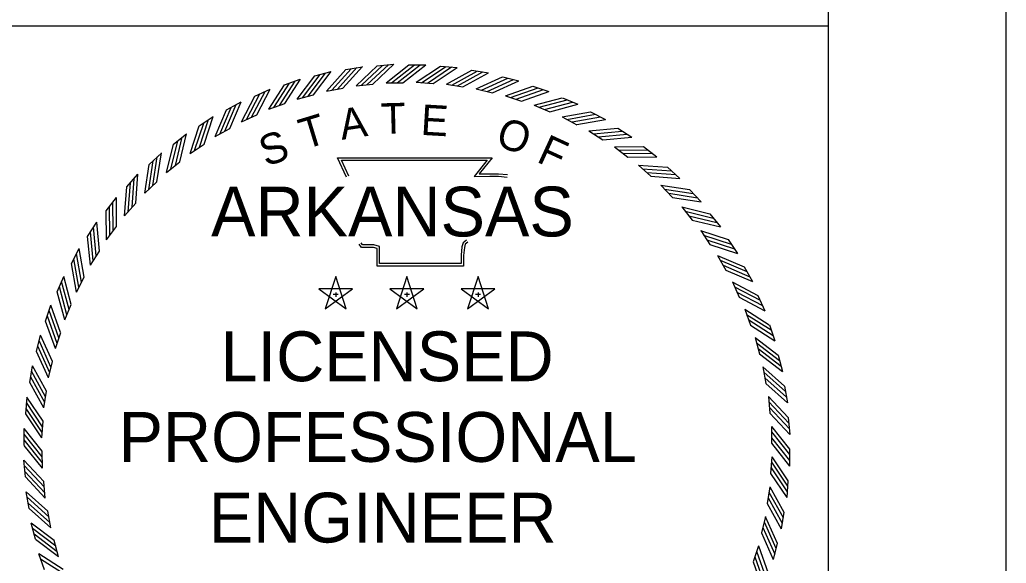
# Model space of a CAD drawing. Extents: x 0 to 1228740, y 0 to 152440.
# Drawn here: x 30.801 to 34, y 18.4 to 20.162 of the extents above; entities that cross this region are included whole.
import ezdxf

# ---------------------------------------------------------------- set-up
doc = ezdxf.new("R2010")
doc.units = 0
doc.layers.add('R_Border', color=7, linetype='Continuous')
doc.layers.add('STAMP', color=7, linetype='Continuous')

msp = doc.modelspace()

# ---------------------------------------------------------------- linework, layer by layer
at = {"layer": 'R_Border'}
for p, q in [((33.4231, 0.5768), (33.4231, 21.4232)), ((29.1131, 20.1432), (33.4231, 20.1432))]:
    msp.add_line(p, q, dxfattribs=at)
msp.add_lwpolyline([(33.9999, 22), (0, 22), (0, 0), (33.9999, 0)], close=True, dxfattribs=at)
at = {"layer": 'STAMP'}
for p, q in [((31.758, 19.9803), (31.8106, 19.9941)), ((31.8584, 20.0008), (31.912, 20.0102)), ((31.9602, 20.013), (32.0144, 20.018)), ((32.0632, 20.016), (32.1176, 20.016)), ((32.1651, 20.0119), (32.2193, 20.0079)), ((32.2668, 19.9987), (32.3205, 19.9903)), ((31.6595, 19.9515), (31.7108, 19.9697)), ((32.367, 19.9772), (32.4199, 19.9643)), ((31.5638, 19.9147), (31.6134, 19.937)), ((31.7954, 19.9309), (31.8491, 19.9404)), ((31.8916, 19.9485), (31.9459, 19.9535)), ((31.989, 19.9581), (32.0435, 19.9581)), ((32.0868, 19.9596), (32.1412, 19.9556)), ((32.1845, 19.9531), (32.2383, 19.9446)), ((32.2812, 19.9385), (32.3342, 19.9256)), ((32.4651, 19.9474), (32.5167, 19.9302)), ((31.7009, 19.9054), (31.7536, 19.9193)), ((32.3764, 19.9159), (32.4281, 19.8987)), ((32.5605, 19.9097), (32.6105, 19.8883)), ((31.4715, 19.8702), (31.5191, 19.8965)), ((31.6089, 19.8722), (31.6603, 19.8904)), ((32.4695, 19.8856), (32.5196, 19.8642)), ((31.3831, 19.8181), (31.4284, 19.8483)), ((31.5199, 19.8315), (31.5696, 19.8539)), ((32.5597, 19.8477), (32.6078, 19.8222)), ((32.6523, 19.8642), (32.7004, 19.8387)), ((31.4346, 19.7836), (31.4823, 19.81)), ((32.6464, 19.8025), (32.6923, 19.7731)), ((32.7402, 19.8112), (32.786, 19.7819)), ((31.2994, 19.759), (31.342, 19.7928)), ((31.3535, 19.7288), (31.3988, 19.7591)), ((32.7292, 19.7503), (32.7725, 19.7172)), ((32.8233, 19.7512), (32.8665, 19.7182)), ((31.2208, 19.6931), (31.2605, 19.7303)), ((31.2772, 19.6675), (31.3199, 19.7014)), ((32.8073, 19.6914), (32.8478, 19.6548)), ((32.9012, 19.6846), (32.9415, 19.6481)), ((31.148, 19.621), (31.1844, 19.6614)), ((31.2063, 19.6001), (31.246, 19.6374)), ((32.8803, 19.6262), (32.9176, 19.5865)), ((32.9733, 19.6117), (33.0105, 19.572)), ((31.0813, 19.5431), (31.1143, 19.5863)), ((31.1411, 19.5271), (31.1777, 19.5676)), ((32.9477, 19.5553), (32.9816, 19.5126)), ((33.0392, 19.5331), (33.073, 19.4905)), ((31.0213, 19.46), (31.0506, 19.5058)), ((31.0822, 19.449), (31.1153, 19.4923)), ((33.009, 19.479), (33.0392, 19.4337)), ((30.9684, 19.3721), (30.9938, 19.4202)), ((33.0983, 19.4494), (33.1285, 19.4041)), ((31.03, 19.3662), (31.0594, 19.4121)), ((33.0638, 19.3979), (33.0902, 19.3502)), ((33.1504, 19.361), (33.1767, 19.3134)), ((30.9228, 19.2803), (30.9442, 19.3303)), ((30.9848, 19.2795), (31.0103, 19.3277)), ((31.8255, 19.3297), (31.7915, 19.2253)), ((31.8594, 19.2254), (31.8256, 19.3298)), ((32.0562, 19.3297), (32.0222, 19.2253)), ((32.0901, 19.2254), (32.0563, 19.3298)), ((32.287, 19.3297), (32.2529, 19.2253)), ((32.3209, 19.2254), (32.287, 19.3298)), ((31.8804, 19.2899), (31.7706, 19.29)), ((31.7707, 19.2899), (31.8594, 19.2252)), ((31.7916, 19.2254), (31.8805, 19.2898)), ((32.1111, 19.2899), (32.0013, 19.29)), ((32.0014, 19.2899), (32.0902, 19.2252)), ((32.0223, 19.2254), (32.1112, 19.2898)), ((32.3418, 19.2899), (32.232, 19.29)), ((32.2321, 19.2899), (32.3209, 19.2252)), ((32.2531, 19.2254), (32.342, 19.2898)), ((33.1117, 19.3126), (33.1341, 19.2629)), ((31.8177, 19.2723), (31.834, 19.2723)), ((31.8256, 19.2782), (31.8256, 19.2644)), ((32.0484, 19.2723), (32.0647, 19.2723)), ((32.0563, 19.2782), (32.0563, 19.2644)), ((32.2791, 19.2723), (32.2955, 19.2723)), ((32.2871, 19.2782), (32.2871, 19.2644)), ((33.1949, 19.2687), (33.2172, 19.2191)), ((30.8851, 19.1849), (30.9023, 19.2365)), ((30.9469, 19.1893), (30.9683, 19.2394)), ((33.1524, 19.2236), (33.1706, 19.1722)), ((33.2317, 19.173), (33.2498, 19.1217)), ((30.8553, 19.0868), (30.8682, 19.1397)), ((30.9166, 19.0962), (30.9338, 19.148)), ((33.1856, 19.1316), (33.1995, 19.0789)), ((33.2605, 19.0745), (33.2743, 19.0219)), ((30.8338, 18.9866), (30.8422, 19.0403)), ((30.894, 19.001), (30.9069, 19.054)), ((33.2111, 19.0371), (33.2206, 18.9835)), ((33.281, 18.9741), (33.2904, 18.9205)), ((30.8206, 18.8849), (30.8246, 18.9391)), ((30.8794, 18.9043), (30.8879, 18.9581)), ((33.2287, 18.9409), (33.2337, 18.8866)), ((30.8729, 18.8066), (30.8769, 18.861)), ((33.2383, 18.8435), (33.2388, 18.789)), ((33.2932, 18.8723), (33.2982, 18.8181)), ((30.8158, 18.7825), (30.8153, 18.8369)), ((30.8744, 18.7088), (30.8739, 18.7633)), ((33.2398, 18.7457), (33.2358, 18.6913)), ((33.2969, 18.7698), (33.2974, 18.7154)), ((30.8195, 18.68), (30.8145, 18.7342)), ((30.884, 18.6114), (30.879, 18.6657)), ((33.2921, 18.6674), (33.2881, 18.6132)), ((30.8317, 18.5782), (30.8223, 18.6318)), ((33.2333, 18.648), (33.2248, 18.5942)), ((30.9016, 18.5152), (30.8921, 18.5689)), ((33.2789, 18.5657), (33.2705, 18.512)), ((30.8522, 18.4778), (30.8384, 18.5304)), ((33.2187, 18.5513), (33.2058, 18.4983)), ((30.9271, 18.4207), (30.9132, 18.4734)), ((33.2574, 18.4655), (33.2445, 18.4126)), ((30.881, 18.3793), (30.8628, 18.4306)), ((33.1961, 18.4561), (33.1789, 18.4044))]:
    msp.add_line(p, q, dxfattribs=at)
for points in [[(31.7535, 19.9193), (31.8106, 19.9942)], [(31.7953, 19.9309), (31.8583, 20.0007)], [(31.8126, 19.9337), (31.8756, 20.0036)], [(31.8311, 19.9374), (31.8941, 20.0073)], [(31.849, 19.9404), (31.912, 20.0103)], [(31.8916, 19.9485), (31.9601, 20.0129)], [(31.909, 19.9499), (31.9776, 20.0144)], [(31.9278, 19.9521), (31.9964, 20.0165)], [(31.9458, 19.9536), (32.0144, 20.018)], [(31.9889, 19.9581), (32.0631, 20.0159)], [(32.0064, 19.9579), (32.0806, 20.0158)], [(32.0253, 19.9583), (32.0995, 20.0162)], [(32.0434, 19.9582), (32.1177, 20.016)], [(32.0868, 19.9596), (32.165, 20.0119)], [(32.1042, 19.9582), (32.1825, 20.0104)], [(32.1231, 19.9572), (32.2013, 20.0095)], [(32.1411, 19.9557), (32.2194, 20.008)], [(32.1844, 19.953), (32.2667, 19.9987)], [(32.2016, 19.9502), (32.284, 19.9958)], [(32.2204, 19.9476), (32.3027, 19.9933)], [(31.643, 19.8845), (31.6937, 19.9638)], [(31.6602, 19.8904), (31.7109, 19.9697)], [(31.7008, 19.9054), (31.7579, 19.9802)], [(31.7178, 19.9096), (31.7749, 19.9845)], [(31.736, 19.9149), (31.793, 19.9897)], [(32.2383, 19.9447), (32.3206, 19.9903)], [(32.2811, 19.9385), (32.3669, 19.9771)], [(32.2981, 19.9342), (32.3839, 19.9728)], [(32.3166, 19.9301), (32.4024, 19.9688)], [(32.3341, 19.9256), (32.4199, 19.9643)], [(31.5529, 19.8466), (31.5969, 19.9298)], [(31.5695, 19.8539), (31.6135, 19.9371)], [(31.6088, 19.8721), (31.6595, 19.9514)], [(31.6254, 19.8778), (31.676, 19.9571)], [(32.3763, 19.9159), (32.465, 19.9474)], [(32.3929, 19.9102), (32.4816, 19.9417)], [(32.411, 19.9047), (32.4997, 19.9361)], [(32.4281, 19.8988), (32.5168, 19.9302)], [(31.5198, 19.8314), (31.5638, 19.9147)], [(31.5359, 19.8385), (31.5798, 19.9217)], [(32.4694, 19.8856), (32.5604, 19.9096)], [(32.4854, 19.8786), (32.5764, 19.9026)], [(31.4345, 19.7835), (31.4714, 19.8701)], [(31.4499, 19.7919), (31.4868, 19.8784)], [(31.4662, 19.8014), (31.5032, 19.8879)], [(31.4822, 19.81), (31.5191, 19.8966)], [(32.5029, 19.8715), (32.5939, 19.8956)], [(32.5195, 19.8642), (32.6105, 19.8883)], [(31.3836, 19.7491), (31.4133, 19.8385)], [(31.3988, 19.759), (31.4284, 19.8484)], [(32.5596, 19.8477), (32.6522, 19.8641)], [(32.575, 19.8394), (32.6676, 19.8558)], [(32.5919, 19.8309), (32.6845, 19.8473)], [(32.6078, 19.8223), (32.7005, 19.8387)], [(31.3535, 19.7287), (31.3831, 19.8181)], [(31.3681, 19.7383), (31.3978, 19.8276)], [(32.6463, 19.8025), (32.7401, 19.8112)], [(32.661, 19.7929), (32.7547, 19.8016)], [(31.291, 19.6782), (31.3132, 19.7697)], [(31.3056, 19.6903), (31.3277, 19.7817)], [(31.3199, 19.7014), (31.342, 19.7929)], [(32.6771, 19.7831), (32.7709, 19.7918)], [(32.6923, 19.7732), (32.786, 19.7819)], [(31.2772, 19.6674), (31.2994, 19.7589)], [(32.7291, 19.7503), (32.8232, 19.7512)], [(32.7429, 19.7395), (32.837, 19.7405)], [(31.2326, 19.6251), (31.2472, 19.7181)], [(31.246, 19.6374), (31.2605, 19.7304)], [(31.8606, 19.652), (31.8316, 19.7147), (32.3332, 19.715), (32.2913, 19.6624), (32.3254, 19.6628), (32.3539, 19.6632), (32.3823, 19.6601)], [(31.8678, 19.6553), (31.844, 19.7068), (32.3167, 19.7071), (32.2747, 19.6542), (32.3255, 19.6549), (32.3535, 19.6552), (32.3814, 19.6522)], [(32.7582, 19.7284), (32.8523, 19.7293)], [(32.7725, 19.7172), (32.8666, 19.7182)], [(31.2063, 19.6001), (31.2208, 19.693)], [(31.2191, 19.6119), (31.2337, 19.7049)], [(32.8072, 19.6914), (32.9011, 19.6846)], [(32.8201, 19.6795), (32.914, 19.6727)], [(31.1653, 19.5542), (31.1722, 19.6481)], [(31.1776, 19.5675), (31.1844, 19.6614)], [(32.8344, 19.6672), (32.9283, 19.6604)], [(32.8477, 19.6549), (32.9416, 19.6481)], [(31.1411, 19.527), (31.1479, 19.6209)], [(31.153, 19.5399), (31.1598, 19.6338)], [(32.8802, 19.6262), (32.9732, 19.6117)], [(32.8921, 19.6134), (32.9851, 19.5988)], [(31.1153, 19.4923), (31.1143, 19.5864)], [(32.9053, 19.5999), (32.9983, 19.5853)], [(32.9176, 19.5865), (33.0106, 19.572)], [(31.093, 19.4627), (31.092, 19.5568)], [(31.1041, 19.478), (31.1032, 19.5721)], [(32.9476, 19.5553), (33.0391, 19.5331)], [(31.0822, 19.4489), (31.0813, 19.543)], [(32.9584, 19.5415), (33.0499, 19.5193)], [(32.9705, 19.5269), (33.0619, 19.5048)], [(31.0494, 19.3969), (31.0407, 19.4907)], [(31.0593, 19.4121), (31.0506, 19.5058)], [(32.9816, 19.5127), (33.073, 19.4905)], [(31.03, 19.3662), (31.0213, 19.4599)], [(31.0396, 19.3808), (31.0309, 19.4745)], [(33.0089, 19.479), (33.0983, 19.4494)], [(33.0185, 19.4644), (33.1078, 19.4347)], [(31.0102, 19.3276), (30.9938, 19.4203)], [(32.2542, 19.4417), (32.2456, 19.4348), (32.2428, 19.4244), (32.2399, 19.3984), (32.2399, 19.3637), (31.9599, 19.3637), (31.9599, 19.4105), (31.9599, 19.4209), (31.9485, 19.4244), (31.9087, 19.4244), (31.9016, 19.4352)], [(32.2492, 19.4479), (32.2386, 19.4393), (32.2349, 19.4259), (32.232, 19.3988), (32.232, 19.3716), (31.9678, 19.3716), (31.9678, 19.4105), (31.9678, 19.4268), (31.9497, 19.4323), (31.913, 19.4323), (31.9083, 19.4395)], [(33.0293, 19.4489), (33.1187, 19.4192)], [(33.0392, 19.4337), (33.1286, 19.4041)], [(30.9931, 19.2948), (30.9767, 19.3875)], [(31.0016, 19.3117), (30.9852, 19.4043)], [(33.0637, 19.398), (33.1503, 19.3611)], [(30.9848, 19.2794), (30.9684, 19.3721)], [(33.0721, 19.3826), (33.1586, 19.3457)], [(33.0816, 19.3663), (33.1681, 19.3293)], [(30.9683, 19.2393), (30.9442, 19.3303)], [(33.0902, 19.3503), (33.1768, 19.3134)], [(30.9539, 19.2052), (30.9299, 19.2962)], [(30.961, 19.2227), (30.9369, 19.3137)], [(33.1116, 19.3127), (33.1949, 19.2687)], [(33.1187, 19.2966), (33.2019, 19.2527)], [(30.9469, 19.1892), (30.9229, 19.2802)], [(33.1268, 19.2796), (33.21, 19.2356)], [(33.1341, 19.263), (33.2173, 19.219)], [(30.9337, 19.1479), (30.9023, 19.2366)], [(30.9223, 19.1127), (30.8908, 19.2014)], [(30.9278, 19.1308), (30.8964, 19.2195)], [(33.1523, 19.2237), (33.2316, 19.173)], [(33.158, 19.2071), (33.2373, 19.1565)], [(30.9166, 19.0961), (30.8851, 19.1848)], [(33.1647, 19.1895), (33.244, 19.1388)], [(33.1706, 19.1723), (33.2499, 19.1217)], [(30.9069, 19.0539), (30.8682, 19.1397)], [(33.1855, 19.1317), (33.2604, 19.0746)], [(30.8983, 19.0179), (30.8597, 19.1037)], [(30.9024, 19.0364), (30.8637, 19.1222)], [(33.1898, 19.1147), (33.2647, 19.0576)], [(30.894, 19.0009), (30.8554, 19.0867)], [(33.1951, 19.0965), (33.2699, 19.0395)], [(33.1995, 19.079), (33.2744, 19.0219)], [(30.8878, 18.9581), (30.8422, 19.0404)], [(33.211, 19.0372), (33.2809, 18.9742)], [(30.8823, 18.9215), (30.8367, 19.0038)], [(30.8849, 18.9402), (30.8392, 19.0225)], [(33.2139, 19.0199), (33.2838, 18.9569)], [(30.8795, 18.9042), (30.8338, 18.9865)], [(33.2176, 19.0014), (33.2875, 18.9384)], [(33.2206, 18.9835), (33.2905, 18.9205)], [(30.8768, 18.8609), (30.8245, 18.9392)], [(33.2287, 18.9409), (33.2931, 18.8724)], [(30.8753, 18.8429), (30.823, 18.9211)], [(33.2301, 18.9235), (33.2945, 18.8549)], [(30.8729, 18.8066), (30.8206, 18.8848)], [(30.8743, 18.824), (30.8221, 18.9023)], [(33.2323, 18.9047), (33.2967, 18.8361)], [(33.2337, 18.8867), (33.2982, 18.8181)], [(33.2383, 18.8436), (33.2968, 18.7699)], [(30.8738, 18.7632), (30.8153, 18.8369)], [(30.8738, 18.7451), (30.8153, 18.8188)], [(33.2383, 18.8261), (33.2968, 18.7524)], [(30.8744, 18.7262), (30.8159, 18.7999)], [(30.8744, 18.7087), (30.8159, 18.7824)], [(33.2389, 18.8072), (33.2974, 18.7335)], [(33.2389, 18.7891), (33.2974, 18.7154)], [(33.2398, 18.7457), (33.2921, 18.6675)], [(30.8789, 18.6656), (30.8145, 18.7342)], [(30.8804, 18.6476), (30.816, 18.7162)], [(33.2383, 18.7283), (33.2906, 18.65)], [(30.8826, 18.6288), (30.8181, 18.6974)], [(33.2359, 18.6914), (33.2882, 18.6131)], [(33.2374, 18.7094), (33.2897, 18.6312)], [(30.884, 18.6114), (30.8196, 18.6799)], [(30.8921, 18.5688), (30.8222, 18.6318)], [(33.2304, 18.6309), (33.276, 18.5485)], [(33.2332, 18.6481), (33.2789, 18.5658)], [(30.8951, 18.5509), (30.8252, 18.6139)], [(30.8988, 18.5324), (30.8289, 18.5954)], [(33.2249, 18.5943), (33.2705, 18.5119)], [(33.2278, 18.6121), (33.2735, 18.5298)], [(30.9017, 18.5151), (30.8318, 18.5781)], [(30.9132, 18.4734), (30.8383, 18.5304)], [(33.2144, 18.5344), (33.253, 18.4486)], [(33.2186, 18.5514), (33.2573, 18.4656)], [(30.9176, 18.4558), (30.8428, 18.5128)], [(30.9229, 18.4376), (30.848, 18.4947)], [(33.2058, 18.4984), (33.2445, 18.4126)], [(33.2103, 18.5159), (33.249, 18.4301)], [(30.9272, 18.4206), (30.8523, 18.4777)], [(30.9421, 18.38), (30.8628, 18.4307)], [(33.1904, 18.4396), (33.2219, 18.3509)], [(33.1961, 18.4562), (33.2276, 18.3675)], [(30.948, 18.3628), (30.8687, 18.4135)], [(33.179, 18.4044), (33.2104, 18.3157)], [(33.1849, 18.4215), (33.2163, 18.3328)]]:
    msp.add_lwpolyline(points, dxfattribs=at)

# ---------------------------------------------------------------- texts
for s, rotation, p in [('A', 8.6788, (31.8453, 19.7727)), ('T', 1.4789, (31.9731, 19.7924)), ('E', 356.672, (32.0997, 19.7894)), ('T', 16.9015, (31.7251, 19.7414)), ('O', 341.2218, (32.34, 19.7555)), ('S', 19.7726, (31.5993, 19.6849)), ('F', 335.3628, (32.4733, 19.7033))]:
    msp.add_text(s, height=0.099, rotation=rotation, dxfattribs=at).set_placement(p)
for s, height, p in [('ARKANSAS', 0.1615, (31.4215, 19.4598)), ('LICENSED', 0.1615, (31.4523, 18.9904)), ('PROFESSIONAL', 0.161501, (31.1216, 18.7289)), ('ENGINEER', 0.1615, (31.4138, 18.4674))]:
    msp.add_text(s, height=height, dxfattribs=at).set_placement(p)

doc.saveas('drawing.dxf')
